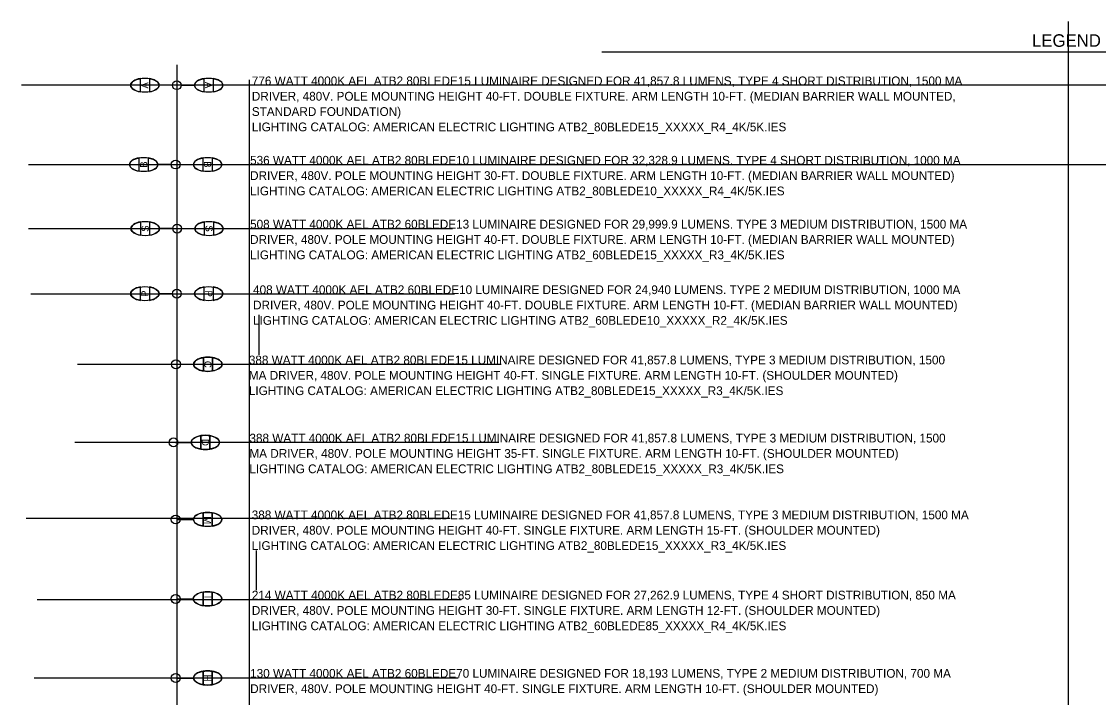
# Model space of a CAD drawing. Extents: x -0.7 to 15.2, y -0.9 to 9.6.
# Drawn here: x -0.65 to 7.94, y 4.21 to 9.6 of the extents above; entities that cross this region are included whole.
import ezdxf

# ---------------------------------------------------------------- set-up
doc = ezdxf.new("R2010")
doc.units = 0
for name, color, linetype in [('ActivePointCell_dp', 7, 'Continuous'), ('Miscellaneous2', 7, 'Continuous'), ('PoleLight', 7, 'Continuous'), ('TextLabel', 7, 'Continuous'), ('TextMisc', 7, 'Continuous')]:
    doc.layers.add(name, color=color, linetype=linetype)

msp = doc.modelspace()

# ---------------------------------------------------------------- linework, layer by layer
at = {"layer": 'ActivePointCell_dp'}
for p, q in [((7.7, -0.9), (7.7, 9.6)), ((0.5844, 9.2534), (0.5844, 0.0367)), ((1.1641, 0.1282), (1.1641, 9.1337)), ((14.876, 9.0917), (-0.6547, 9.0917)), ((0.5844, 9.0917), (0.5844, 6.27)), ((14.8669, 8.4563), (-0.599, 8.4563)), ((2.7845, 7.9463), (-0.599, 7.9463)), ((2.8019, 7.4241), (-0.5816, 7.4241)), ((1.2412, 6.9409), (1.2412, 7.2583)), ((3.1743, 6.8635), (-0.2092, 6.8635)), ((3.1545, 6.24), (-0.229, 6.24)), ((2.7664, 5.6341), (-0.6171, 5.6341)), ((1.2213, 5.0615), (1.2213, 5.3789)), ((2.853, 4.9857), (-0.5305, 4.9857)), ((2.8302, 4.3595), (-0.5533, 4.3595))]:
    msp.add_line(p, q, dxfattribs=at)
at = {"layer": 'Miscellaneous2'}
for centre in [(0.8323, 6.8646), (0.8124, 6.2411), (0.83, 5.6261), (0.8296, 4.9921), (0.8303, 4.3609)]:
    msp.add_ellipse(centre, major_axis=(-0.1133, 0), ratio=0.5, start_param=4.391241, end_param=4.391271, dxfattribs=at)
at = {"layer": 'PoleLight'}
for p, q in [((0.2938, 9.038), (0.2938, 9.1454)), ((0.3653, 9.1454), (0.3653, 9.038)), ((0.8034, 9.038), (0.8034, 9.1454)), ((0.8749, 9.1454), (0.8749, 9.038)), ((0.549, 9.0917), (0.4428, 9.0917)), ((0.6197, 9.0917), (0.7259, 9.0917)), ((0.2847, 8.4048), (0.2847, 8.5122)), ((0.3562, 8.5122), (0.3562, 8.4048)), ((0.7943, 8.4048), (0.7943, 8.5122)), ((0.8658, 8.5122), (0.8658, 8.4048)), ((0.5399, 8.4585), (0.4337, 8.4585)), ((0.6107, 8.4585), (0.7168, 8.4585)), ((0.2963, 7.8937), (0.2963, 8.0011)), ((0.3678, 8.0011), (0.3678, 7.8937)), ((0.8059, 7.8937), (0.8059, 8.0011)), ((0.8774, 8.0011), (0.8774, 7.8937)), ((0.5515, 7.9474), (0.4453, 7.9474)), ((0.6223, 7.9474), (0.7284, 7.9474)), ((0.2939, 7.3743), (0.2939, 7.4817)), ((0.3654, 7.4817), (0.3654, 7.3743)), ((0.8036, 7.3743), (0.8036, 7.4817)), ((0.8751, 7.4817), (0.8751, 7.3743)), ((0.5491, 7.428), (0.4429, 7.428)), ((0.6199, 7.428), (0.7261, 7.428)), ((0.7965, 6.8109), (0.7965, 6.9184)), ((0.7965, 6.9172), (0.7965, 6.8109)), ((0.868, 6.9184), (0.868, 6.8109)), ((0.868, 6.8109), (0.868, 6.9184)), ((0.5929, 6.8643), (0.7238, 6.8643)), ((0.7767, 6.1874), (0.7767, 6.2949)), ((0.7767, 6.2937), (0.7767, 6.1874)), ((0.8482, 6.2949), (0.8482, 6.1874)), ((0.8482, 6.1874), (0.8482, 6.2949)), ((0.573, 6.2408), (0.704, 6.2408)), ((0.7943, 5.5723), (0.7943, 5.6798)), ((0.7943, 5.6786), (0.7943, 5.5723)), ((0.8658, 5.6798), (0.8658, 5.5723)), ((0.8658, 5.5723), (0.8658, 5.6798)), ((0.5906, 5.6257), (0.7216, 5.6257)), ((0.5902, 4.9917), (0.7212, 4.9917)), ((0.7939, 4.9384), (0.7939, 5.0458)), ((0.7939, 5.0446), (0.7939, 4.9384)), ((0.8654, 5.0458), (0.8654, 4.9384)), ((0.8654, 4.9384), (0.8654, 5.0458)), ((0.7946, 4.3071), (0.7946, 4.4146)), ((0.7946, 4.4134), (0.7946, 4.3071)), ((0.8661, 4.4146), (0.8661, 4.3071)), ((0.8661, 4.3071), (0.8661, 4.4146)), ((0.5909, 4.3605), (0.7219, 4.3605))]:
    msp.add_line(p, q, dxfattribs=at)
for centre in [(0.5844, 9.0917), (0.5844, 9.0917), (0.5753, 8.4585), (0.5753, 8.4585), (0.5869, 7.9474), (0.5869, 7.9474), (0.5845, 7.428), (0.5845, 7.428), (0.5779, 6.8643), (0.5779, 6.8643), (0.5581, 6.2408), (0.5581, 6.2408), (0.5756, 5.6257), (0.5756, 5.6257), (0.5753, 4.9917), (0.5753, 4.9917), (0.576, 4.3605), (0.576, 4.3605)]:
    msp.add_circle(centre, 0.0354, dxfattribs=at)
for centre, major_axis in [((0.3295, 9.0917), (0.1133, 0)), ((0.8392, 9.0917), (0.1133, 0)), ((0.3204, 8.4585), (0.1133, 0)), ((0.8301, 8.4585), (0.1133, 0)), ((0.332, 7.9474), (0.1133, 0)), ((0.8417, 7.9474), (0.1133, 0)), ((0.3297, 7.428), (0.1133, 0)), ((0.8393, 7.428), (0.1133, 0)), ((0.8323, 6.8646), (-0.1133, 0)), ((0.8124, 6.2411), (-0.1133, 0)), ((0.83, 5.6261), (-0.1133, 0)), ((0.8296, 4.9921), (-0.1133, 0)), ((0.8303, 4.3609), (-0.1133, 0))]:
    msp.add_ellipse(centre, major_axis=major_axis, ratio=0.5, dxfattribs=at)
for centre, major_axis, start_param, end_param in [((0.3295, 9.0917), (0.1133, 0), 1.891945, 4.391241), ((0.3295, 9.0917), (0.1133, 0), 0.847605, 1.249648), ((0.3295, 9.0917), (0.1133, 0), 0, 0.847605), ((0.8392, 9.0917), (0.1133, 0), 1.891945, 4.391241), ((0.8392, 9.0917), (0.1133, 0), 0.847605, 1.249648), ((0.8392, 9.0917), (0.1133, 0), 0, 0.847605), ((0.3295, 9.0917), (0.1133, 0), 5.033538, 6.283185), ((0.8392, 9.0917), (0.1133, 0), 5.033538, 6.283185), ((0.3204, 8.4585), (0.1133, 0), 1.891945, 4.391241), ((0.3204, 8.4585), (0.1133, 0), 0.847605, 1.249648), ((0.8301, 8.4585), (0.1133, 0), 1.891945, 4.391241), ((0.8301, 8.4585), (0.1133, 0), 0.847605, 1.249648), ((0.3204, 8.4585), (0.1133, 0), 5.033538, 6.283185), ((0.3204, 8.4585), (0.1133, 0), 0, 0.847605), ((0.8301, 8.4585), (0.1133, 0), 5.033538, 6.283185), ((0.8301, 8.4585), (0.1133, 0), 0, 0.847605), ((0.332, 7.9474), (0.1133, 0), 1.891945, 4.391241), ((0.332, 7.9474), (0.1133, 0), 0.847605, 1.249648), ((0.8417, 7.9474), (0.1133, 0), 1.891945, 4.391241), ((0.8417, 7.9474), (0.1133, 0), 0.847605, 1.249648), ((0.332, 7.9474), (0.1133, 0), 5.033538, 6.283185), ((0.332, 7.9474), (0.1133, 0), 0, 0.847605), ((0.8417, 7.9474), (0.1133, 0), 5.033538, 6.283185), ((0.8417, 7.9474), (0.1133, 0), 0, 0.847605), ((0.3297, 7.428), (0.1133, 0), 1.891945, 4.391241), ((0.3297, 7.428), (0.1133, 0), 0.847605, 1.249648), ((0.8393, 7.428), (0.1133, 0), 1.891945, 4.391241), ((0.8393, 7.428), (0.1133, 0), 0.847605, 1.249648), ((0.3297, 7.428), (0.1133, 0), 5.033538, 6.283185), ((0.3297, 7.428), (0.1133, 0), 0, 0.847605), ((0.8393, 7.428), (0.1133, 0), 5.033538, 6.283185), ((0.8393, 7.428), (0.1133, 0), 0, 0.847605), ((0.8323, 6.8646), (-0.1133, 0), 5.033538, 6.283185), ((0.8323, 6.8646), (-0.1133, 0), 4.391271, 5.033538), ((0.8323, 6.8646), (-0.1133, 0), 1.891945, 4.391241), ((0.8323, 6.8646), (-0.1133, 0), 0, 0.847605), ((0.8323, 6.8646), (-0.1133, 0), 0.847605, 1.249648), ((0.8323, 6.8646), (-0.1133, 0), 1.249648, 1.891946), ((0.8124, 6.2411), (-0.1133, 0), 5.033538, 6.283185), ((0.8124, 6.2411), (-0.1133, 0), 4.391271, 5.033538), ((0.8124, 6.2411), (-0.1133, 0), 1.891945, 4.391241), ((0.8124, 6.2411), (-0.1133, 0), 0, 0.847605), ((0.8124, 6.2411), (-0.1133, 0), 0.847605, 1.249648), ((0.8124, 6.2411), (-0.1133, 0), 1.249648, 1.891946), ((0.83, 5.6261), (-0.1133, 0), 5.033538, 6.283185), ((0.83, 5.6261), (-0.1133, 0), 4.391271, 5.033538), ((0.83, 5.6261), (-0.1133, 0), 1.891945, 4.391241), ((0.83, 5.6261), (-0.1133, 0), 0, 0.847605), ((0.83, 5.6261), (-0.1133, 0), 0.847605, 1.249648), ((0.8296, 4.9921), (-0.1133, 0), 5.033538, 6.283185), ((0.8296, 4.9921), (-0.1133, 0), 0, 0.847605), ((0.8296, 4.9921), (-0.1133, 0), 4.391271, 5.033538), ((0.8296, 4.9921), (-0.1133, 0), 1.891945, 4.391241), ((0.8296, 4.9921), (-0.1133, 0), 0.847605, 1.249648), ((0.8296, 4.9921), (-0.1133, 0), 1.249648, 1.891946), ((0.8303, 4.3609), (-0.1133, 0), 5.033538, 6.283185), ((0.8303, 4.3609), (-0.1133, 0), 4.391271, 5.033538), ((0.8303, 4.3609), (-0.1133, 0), 1.891945, 4.391241), ((0.8303, 4.3609), (-0.1133, 0), 0, 0.847605), ((0.8303, 4.3609), (-0.1133, 0), 0.847605, 1.249648), ((0.8303, 4.3609), (-0.1133, 0), 1.249648, 1.891946)]:
    msp.add_ellipse(centre, major_axis=major_axis, ratio=0.5, start_param=start_param, end_param=end_param, dxfattribs=at)
at = {"layer": 'TextLabel'}
msp.add_line((3.9762, 9.3579), (12.0301, 9.3579), dxfattribs=at)

# ---------------------------------------------------------------- texts
for s, rotation, p in [('A', 90, (0.3581, 9.065)), ('A', 270, (0.8106, 9.1183)), ('B', 90, (0.349, 8.4324)), ('B', 270, (0.8015, 8.4846)), ('S', 90, (0.3606, 7.9218)), ('S', 270, (0.8131, 7.973)), ('P', 90, (0.3583, 7.4022)), ('P', 270, (0.8107, 7.4538)), ('C', 270.00005, (0.8037, 6.8914)), ('D', 270.00005, (0.7838, 6.268)), ('M', 270.00005, (0.8014, 5.6525)), ('I', 270.00005, (0.8028, 5.0177)), ('H', 270.00005, (0.8017, 4.387))]:
    msp.add_text(s, height=0.0572, rotation=rotation, dxfattribs=at).set_placement(p)
at = {"layer": 'TextMisc'}
for s, height, p in [('LEGEND', 0.1, (7.4095, 9.3984)), ('776 WATT 4000K AEL ATB2 80BLEDE15 LUMINAIRE DESIGNED FOR 41,857.8 LUMENS, TYPE 4 SHORT DISTRIBUTION, 1500 MA ', 0.07, (1.1832, 9.0913)), ('DRIVER, 480V. POLE MOUNTING HEIGHT 40-FT. DOUBLE FIXTURE. ARM LENGTH 10-FT. (MEDIAN BARRIER WALL MOUNTED, ', 0.07, (1.1832, 8.9688)), ('STANDARD FOUNDATION)', 0.07, (1.1832, 8.8463)), ('LIGHTING CATALOG: AMERICAN ELECTRIC LIGHTING ATB2_80BLEDE15_XXXXX_R4_4K/5K.IES', 0.07, (1.1832, 8.7238)), ('536 WATT 4000K AEL ATB2 80BLEDE10 LUMINAIRE DESIGNED FOR 32,328.9 LUMENS. TYPE 4 SHORT DISTRIBUTION, 1000 MA ', 0.07, (1.1693, 8.4578)), ('DRIVER, 480V. POLE MOUNTING HEIGHT 30-FT. DOUBLE FIXTURE. ARM LENGTH 10-FT. (MEDIAN BARRIER WALL MOUNTED)', 0.07, (1.1693, 8.3353)), ('LIGHTING CATALOG: AMERICAN ELECTRIC LIGHTING ATB2_80BLEDE10_XXXXX_R4_4K/5K.IES', 0.07, (1.1693, 8.2128)), ('508 WATT 4000K AEL ATB2 60BLEDE13 LUMINAIRE DESIGNED FOR 29,999.9 LUMENS. TYPE 3 MEDIUM DISTRIBUTION, 1500 MA ', 0.07, (1.1693, 7.9478)), ('DRIVER, 480V. POLE MOUNTING HEIGHT 40-FT. DOUBLE FIXTURE. ARM LENGTH 10-FT. (MEDIAN BARRIER WALL MOUNTED)', 0.07, (1.1693, 7.8253)), ('LIGHTING CATALOG: AMERICAN ELECTRIC LIGHTING ATB2_60BLEDE15_XXXXX_R3_4K/5K.IES', 0.07, (1.1693, 7.7028)), ('408 WATT 4000K AEL ATB2 60BLEDE10 LUMINAIRE DESIGNED FOR 24,940 LUMENS. TYPE 2 MEDIUM DISTRIBUTION, 1000 MA ', 0.07, (1.1931, 7.4246)), ('DRIVER, 480V. POLE MOUNTING HEIGHT 40-FT. DOUBLE FIXTURE. ARM LENGTH 10-FT. (MEDIAN BARRIER WALL MOUNTED)', 0.07, (1.1931, 7.3021)), ('LIGHTING CATALOG: AMERICAN ELECTRIC LIGHTING ATB2_60BLEDE10_XXXXX_R2_4K/5K.IES', 0.07, (1.1931, 7.1796)), ('388 WATT 4000K AEL ATB2 80BLEDE15 LUMINAIRE DESIGNED FOR 41,857.8 LUMENS, TYPE 3 MEDIUM DISTRIBUTION, 1500 ', 0.07, (1.1594, 6.8636)), ('MA DRIVER, 480V. POLE MOUNTING HEIGHT 40-FT. SINGLE FIXTURE. ARM LENGTH 10-FT. (SHOULDER MOUNTED)', 0.07, (1.1594, 6.7411)), ('LIGHTING CATALOG: AMERICAN ELECTRIC LIGHTING ATB2_80BLEDE15_XXXXX_R3_4K/5K.IES', 0.07, (1.1594, 6.6186)), ('388 WATT 4000K AEL ATB2 80BLEDE15 LUMINAIRE DESIGNED FOR 41,857.8 LUMENS, TYPE 3 MEDIUM DISTRIBUTION, 1500 ', 0.07, (1.1641, 6.2403)), ('MA DRIVER, 480V. POLE MOUNTING HEIGHT 35-FT. SINGLE FIXTURE. ARM LENGTH 10-FT. (SHOULDER MOUNTED)', 0.07, (1.1641, 6.1178)), ('LIGHTING CATALOG: AMERICAN ELECTRIC LIGHTING ATB2_80BLEDE15_XXXXX_R3_4K/5K.IES', 0.07, (1.1641, 5.9953)), ('388 WATT 4000K AEL ATB2 80BLEDE15 LUMINAIRE DESIGNED FOR 41,857.8 LUMENS, TYPE 3 MEDIUM DISTRIBUTION, 1500 MA ', 0.07, (1.1824, 5.6273)), ('DRIVER, 480V. POLE MOUNTING HEIGHT 40-FT. SINGLE FIXTURE. ARM LENGTH 15-FT. (SHOULDER MOUNTED)', 0.07, (1.1824, 5.5048)), ('LIGHTING CATALOG: AMERICAN ELECTRIC LIGHTING ATB2_80BLEDE15_XXXXX_R3_4K/5K.IES', 0.07, (1.1824, 5.3823)), ('214 WATT 4000K AEL ATB2 80BLEDE85 LUMINAIRE DESIGNED FOR 27,262.9 LUMENS, TYPE 4 SHORT DISTRIBUTION, 850 MA ', 0.07, (1.1832, 4.9872)), ('DRIVER, 480V. POLE MOUNTING HEIGHT 30-FT. SINGLE FIXTURE. ARM LENGTH 12-FT. (SHOULDER MOUNTED)', 0.07, (1.1832, 4.8647)), ('LIGHTING CATALOG: AMERICAN ELECTRIC LIGHTING ATB2_60BLEDE85_XXXXX_R4_4K/5K.IES', 0.07, (1.1832, 4.7422)), ('130 WATT 4000K AEL ATB2 60BLEDE70 LUMINAIRE DESIGNED FOR 18,193 LUMENS, TYPE 2 MEDIUM DISTRIBUTION, 700 MA ', 0.07, (1.1699, 4.3626)), ('DRIVER, 480V. POLE MOUNTING HEIGHT 40-FT. SINGLE FIXTURE. ARM LENGTH 10-FT. (SHOULDER MOUNTED)', 0.07, (1.1699, 4.2401))]:
    msp.add_text(s, height=height, dxfattribs=at).set_placement(p)

doc.saveas('drawing.dxf')
